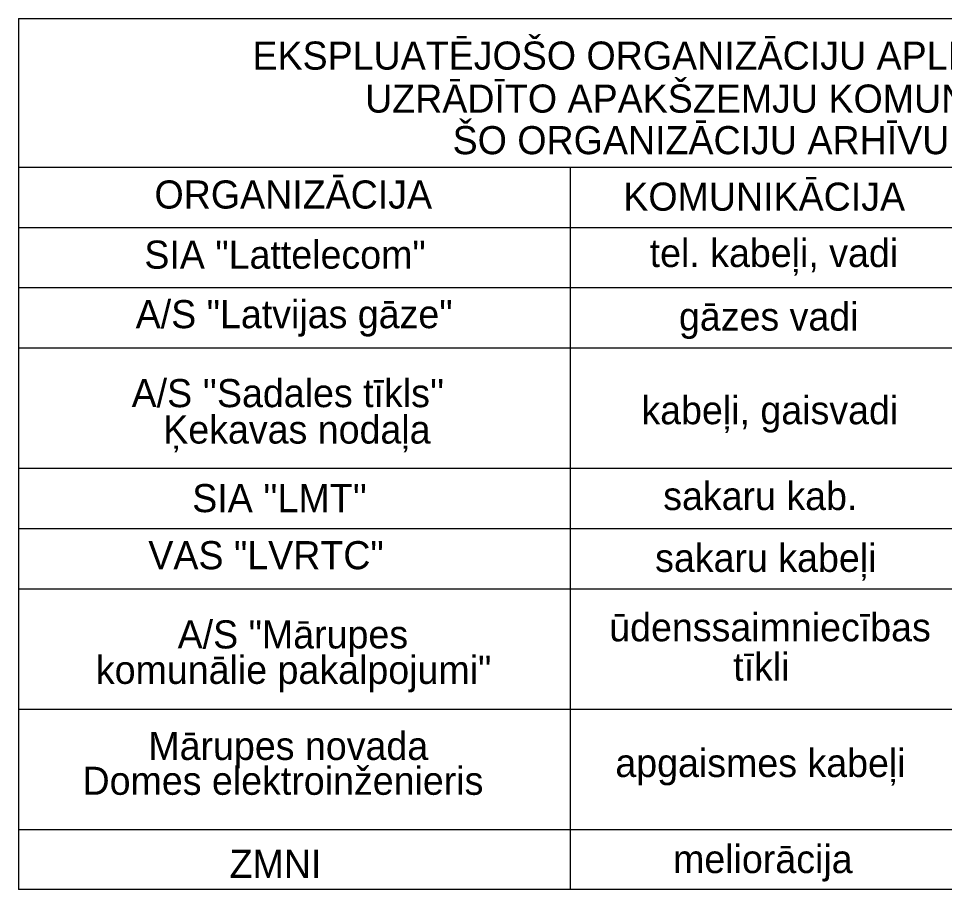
# Model space of a CAD drawing. Extents: x 496078 to 496285, y 304225 to 304369.
# Drawn here: x 496221.31 to 496254.27, y 304250.61 to 304281.59 of the extents above; entities that cross this region are included whole.
import ezdxf

# ---------------------------------------------------------------- set-up
doc = ezdxf.new("R2010")
doc.units = 0
doc.layers.add('RAMI_PLAN_####_TKST_#', color=7, linetype='Continuous')

msp = doc.modelspace()

# ---------------------------------------------------------------- linework, layer by layer
at = {"layer": 'RAMI_PLAN_####_TKST_#'}
for p, q in [((496221.306, 304281.594), (496282.865, 304281.594)), ((496221.306, 304281.594), (496221.306, 304250.614)), ((496282.865, 304276.294), (496221.306, 304276.294)), ((496240.944, 304276.294), (496240.944, 304250.614)), ((496282.865, 304274.152), (496221.306, 304274.152)), ((496282.865, 304272.009), (496221.306, 304272.009)), ((496282.865, 304269.867), (496221.306, 304269.867)), ((496282.865, 304265.583), (496221.306, 304265.583)), ((496282.865, 304263.441), (496221.306, 304263.441)), ((496282.865, 304261.301), (496221.306, 304261.301)), ((496282.865, 304257.021), (496221.306, 304257.021)), ((496282.865, 304252.741), (496221.306, 304252.741)), ((496282.865, 304250.614), (496221.306, 304250.614))]:
    msp.add_line(p, q, dxfattribs=at)

# ---------------------------------------------------------------- texts
for s, p in [(' EKSPLUATĒJOŠO ORGANIZĀCIJU APLIECINĀJUMS PAR PLĀNĀ', (496229.262, 304279.776)), (' UZRĀDĪTO APAKŠZEMJU KOMUNIKĀCIJU ATBILSTĪBU', (496233.272, 304278.247)), (' ŠO ORGANIZĀCIJU ARHĪVU MATERIĀLIEM', (496236.387, 304276.768)), ('ORGANIZĀCIJA', (496226.146, 304274.835)), ('KOMUNIKĀCIJA', (496242.835, 304274.759)), ('SIA "Lattelecom"', (496225.785, 304272.696)), ('tel. kabeļi, vadi', (496243.773, 304272.755)), ('A/S "Latvijas gāze"', (496225.477, 304270.579)), ('gāzes vadi', (496244.816, 304270.495)), ("A/S ''Sadales tīkls'' ", (496225.332, 304267.77)), ('kabeļi, gaisvadi', (496243.479, 304267.163)), ('Ķekavas nodaļa', (496226.458, 304266.475)), ('sakaru kab.', (496244.255, 304264.111)), ("SIA ''LMT''", (496227.489, 304264.035))]:
    msp.add_text(s, height=1, dxfattribs=at).set_placement(p)
for s, p in [('VAS "LVRTC"', (496225.927, 304262.005)), ('sakaru kabeļi', (496243.967, 304261.91)), ('ūdenssaimniecības', (496242.334, 304259.442)), ('A/S "Mārupes', (496226.97, 304259.187)), ('komunālie pakalpojumi"', (496224.061, 304257.927)), ('tīkli', (496246.749, 304258.037)), ('Mārupes novada', (496225.928, 304255.221)), ('apgaismes kabeļi', (496242.552, 304254.614)), ('Domes elektroinženieris', (496223.585, 304253.981)), ('meliorācija', (496244.606, 304251.197)), ('ZMNI', (496228.82, 304251.024))]:
    msp.add_text(s, height=1, rotation=359.9987, dxfattribs=at).set_placement(p)

doc.saveas('drawing.dxf')
